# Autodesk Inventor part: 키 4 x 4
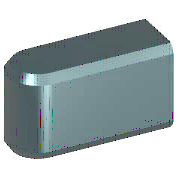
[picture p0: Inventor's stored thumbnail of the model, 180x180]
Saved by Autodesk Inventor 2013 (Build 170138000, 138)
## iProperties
IsCustomPart: 1
Created: 2012-02
Part Number: 키 4 x 4
Material: 강철, 연강
Description: 키 및 해당 키홈
Document SubType Name: Modeling
Standard: KS B 1311
Designer: mduedu
Standards Organization: KS
Language: ko-KR
Size Designation: 4 x 4 x 18
Categories: <MemberInstance><Categories><Category DisplayName="샤프트 부품" InternalName="7f7aeb1f-a693-4053-b835-cee3144e0d98" Mnemonic="SHFT"><Category DisplayName="키" Interna
Density: 1 g/cm^3
Author: mduedu
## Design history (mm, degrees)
sketch "스케치1"
  geometry: L1 (2, 2)-(18, 2); L2 (18, 2)-(18, -2); L3 (18, -2)-(2, -2); L4 (0, 7)-(0, -7) reference; L5 (-5, 0)-(30, 0) reference; A1 r 2 centre (2, 0) between (2, 2) and (2, -2)
  constraints: 6 end point, 3 tangent, 2 point on circle, 1 centre point, 1 horizontal, 1 parallel, 1 perpendicular, 1 point on line
  dimensions: "d0" = 2 radius of A1 (= 0.5 x PB); "d7" = 18 distance between parallel lines of L2 L4 (= NLG)
workplane "Work Plane1"
workplane "Work Plane2"
extrude "본체1" new body sketch "스케치1" taper "d3" = 0 deg; stored distance "d4" = 10
workaxis "Work Axis1"
workplane "Work Plane4"
body "Solid1"
chamfer "모따기1" distance "d8" = 0.25 (= PHH); stored, may be unused: second distance "d9" = 0.25 (= PHH), angle "d13" = 45 deg
other parameters: "d1" = -2.5 (= -PNT), "d2" = 1.5 (= PH - PNT), "NLG" = 18 [user parameter; used in 2 equation terms], "PB" = 4 [user parameter; used in 1 equation term], "PNT" = 2.5 [user parameter; used in 2 equation terms], "PH" = 4 [user parameter; used in 1 equation term], "PHH" = 0.25 [user parameter; used in 2 equation terms], "d10" = 0, "d16" = 0, "d17" = 0, "d18" = 0, "RR" = 0.08 [user parameter], "WDMAX" = 12 [user parameter], "PLB1" = 18 (= NLG) [user parameter], "PUEB" = 1.8 [user parameter]
